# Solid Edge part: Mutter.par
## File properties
Sűrűség: 0,000 kg/m^3
Pontosság: 0,990
Author: ahadarics
Last saved by: psaghy
Revision: 77
Username: ahadarics
Dokumentum tartalom típus: 0
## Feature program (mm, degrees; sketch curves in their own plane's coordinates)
base feature "unnamed BaseFeature 1"
sketch for "Furat_1" plane through (0, 0, 0) normal (-1, 0, 0) x-axis (0, 0, -1)
hole "Furat_1" through  StartChamferOffset = 0.92 mm; StartChamferAngle = 45 deg
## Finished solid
Body 1: solid body, 23 faces, 47 edges, 26 vertices.
  Faces by surface: cone 14, plane 8, cylinder 1
  Edges by curve: spline 24, circle 16, line 7
Bounding box of the edges (mm): 14.000 x 63.508 x 55.000, from (0, -31.7543, -27.5) to (14, 31.7543, 27.5).
Cylindrical faces by radius (mm): R16.9175 x1
Conical faces (half-angle, radius in mm at the cone's reference point): 45 deg R17.8375 x1, 60 deg R17.1881 x1, 60 deg R29.6271 x12
Planar faces by outward normal: +x 1, +z 1, -x 1, -z 1, oblique 4
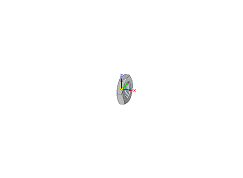
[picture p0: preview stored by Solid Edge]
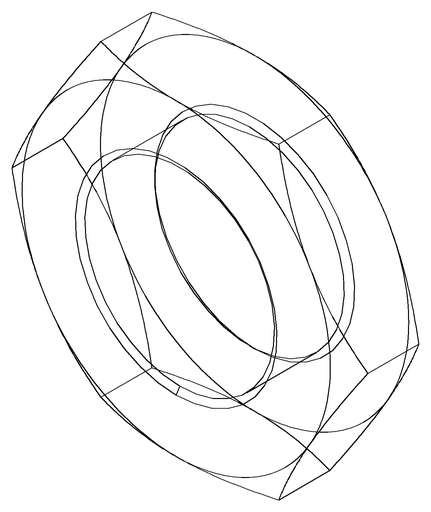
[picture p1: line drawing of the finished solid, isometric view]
